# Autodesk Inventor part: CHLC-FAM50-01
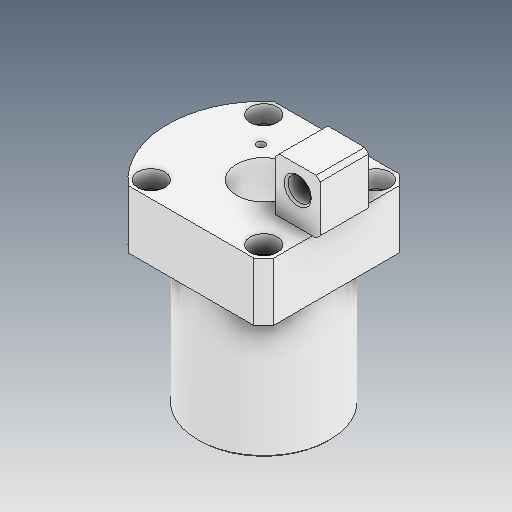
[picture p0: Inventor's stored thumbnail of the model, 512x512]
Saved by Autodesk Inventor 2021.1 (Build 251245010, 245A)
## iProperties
Created: 2021-05
Part Number: CHLC-FAM50-01
Material: Ogólny
Document SubType Name: Modeling
Designer: user
Density: 1 g/cm^3
Appearance: Domyślna
Author: user
Revision Number: ÈÎºÎ
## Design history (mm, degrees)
feature "NONE"
feature "Złożony1"
node "Bryła1"
body "Srf1"
